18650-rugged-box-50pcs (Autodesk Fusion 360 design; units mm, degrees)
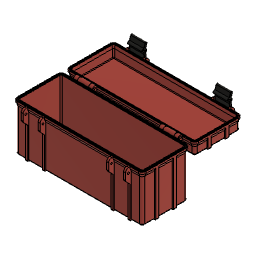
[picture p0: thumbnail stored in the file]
parameter "InnerBoxDepth" = 67 comment "Inner depth"
parameter "InnerBoxWidth" = 195 comment "Inner width"
parameter "InnerBoxBottomHeight" = 73 comment "Inner height of the bottom part"
parameter "ScrewDiameter" = 3 comment "M3 => 3 mm"
parameter "InnerCornerRadius" = 0.75 comment "Corner radius on the bottom (bottom of champfer)"
parameter "HingeLatchOffset" = 15 comment "Offset of the hinge and latch from inner wall"
parameter "WallThickness" = 2.4 comment "Thickness of the walls"
parameter "RibWidth" = 5 comment "Width of the ribs on the sides"
parameter "InnerChamferSize" = 1 comment "Size of the chamfer on the top and bottom inside the box"
parameter "ScrewThreadDiameter" = 2.85 (= "ScrewDiameter - 0.15 mm") comment "Diameter of the inner holes where you screw in the screw"
parameter "ScrewLength" = 30 comment "Length of the screw to use"
parameter "HingeWidthTolerance" = 0.25 comment "Tolerance of the hinge (width)"
parameter "RibOffset" = 17 comment "Offset of the ribs from inner wall"
parameter "LatchDistance" = 16 comment "Distance between the two screws of the latch"
parameter "InnerBoxLidHeight" = 18 comment "Inner height of the lid"
parameter "HingeLatchHolesTolerance" = 0.4 comment "Tolerance of the hinge and latch holes"
parameter "LatchWidthTolerance" = 0.4 comment "Tollerance of the latch width"
parameter "SealHeight" = 1.4 comment "Height of the seal"
parameter "HingeLatchRibWidth" = 3.2 comment "Width of the ribs for the hinges and latches"
parameter "BoxLatchRibChamferOffset" = 17
parameter "HingeRibChamferOffset" = 5 comment "Offset of the big chamfer on the rib of the hinge side"
parameter "HingeOuterDiameter" = 6.8
parameter "LidLatchRibChamferOffset" = 10 comment "Offset of the big chamfer on the rib of the lid"
parameter "HingeOuterExtend" = 3
sketch "Sketch1" plane through (0, 0, 0) normal (0, 1, 0) x axis (1, 0, 0)
  line L1 (-31.75, -96.5) -> (31.75, -96.5)
  line L2 (-32.5, 95.75) -> (-32.5, -95.75)
  line L3 (31.75, 96.5) -> (-31.75, 96.5)
  line L4 (32.5, -95.75) -> (32.5, 95.75)
  line L5 (-32.5, 96.5) -> (32.5, -96.5)
  line L6 (32.5, 96.5) -> (-32.5, -96.5)
  arc A1 centre (-31.75, 95.75) radius 0.75 clockwise from (-32.5, 95.75) to (-31.75, 96.5)
  arc A2 centre (31.75, 95.75) radius 0.75 clockwise from (31.75, 96.5) to (32.5, 95.75)
  arc A3 centre (31.75, -95.75) radius 0.75 clockwise from (32.5, -95.75) to (31.75, -96.5)
  arc A4 centre (-31.75, -95.75) radius 0.75 clockwise from (-31.75, -96.5) to (-32.5, -95.75)
  point P6 (0, 0)
  point P1 (0, 0)
  point P4 (-32.5, 96.5)
  point P5 (32.5, 96.5)
  point P2 (32.5, -96.5)
  point P3 (-32.5, -96.5)
  horizontal L1
  perpendicular L1 L2
  parallel L1 L3
  parallel L2 L4
  coincident L5 P6
  coincident L6 P6
  coincident P1 P6
  coincident P4 L3
  coincident P4 L2
  tangent L3 A1
  tangent L2 A1
  coincident P5 L3
  coincident P5 L4
  tangent L3 A2
  tangent L4 A2
  coincident P2 L4
  coincident P2 L1
  tangent L4 A3
  tangent L1 A3
  coincident P3 L1
  coincident P3 L2
  tangent L1 A4
  tangent L2 A4
  equal A1 A2
  equal A1 A4
  equal A3 A4
  dimension "d6" distance L1 L3 = 193 (= "InnerBoxWidth - 2 * InnerChamferSize")
  dimension "d7" distance L2 L4 = 65 (= "InnerBoxDepth - 2 * InnerChamferSize")
  dimension "d9" radius A2 = 0.75 (= "InnerCornerRadius")
sketch "Sketch2" plane through (0, 0, 0) normal (0, 0, 1) x axis (1, 0, 0)
  line L1 (32.5, 0) -> (0, 0)
  line L2 (32.5, 2.4) -> (32.5, 0)
  line L3 (33.5, 75.4) -> (33.5, 3.4)
  line L4 (34.73, 75.4) -> (33.5, 75.4)
  line L5 (34.73, 73.4) -> (34.73, 75.4)
  line L6 (36.53, 73.4) -> (34.73, 73.4)
  line L7 (36.53, 75.4) -> (36.53, 73.4)
  line L8 (37.76, 75.4) -> (36.53, 75.4)
  line L9 (37.76, 72.4) -> (37.76, 75.4)
  line L10 (32.5, 0) -> (42.6865, 0)
  line L11 (35.9, 72.4) -> (37.76, 72.4)
  line L12 (35.9, 68) -> (35.9, 72.4)
  line L13 (35.9, 2.4059) -> (35.9, 68)
  line L14 (37.76, 72.4) -> (35.9, 68)
  line L15 (32.5, 2.4) -> (33.5, 3.4)
  line L16 (35.9, 2.4059) -> (33.4941, 0)
  line L17 (44.76, 2.0735) -> (42.6865, 0)
  line L18 (39.76, 75.4) -> (37.76, 75.4)
  line L19 (44.76, 2.0735) -> (44.76, 70.4)
  line L20 (0, 60) -> (0, 0)
  line L21 (-44.76, 2.0735) -> (-44.76, 70.4)
  line L22 (-34.73, 73.4) -> (-34.73, 75.4)
  line L23 (-37.76, 72.4) -> (-35.9, 68)
  line L24 (-33.5, 75.4) -> (-33.5, 3.4)
  line L25 (-32.5, 2.4) -> (-32.5, 0)
  line L26 (-36.53, 73.4) -> (-34.73, 73.4)
  line L27 (-35.9, 2.4059) -> (-33.4941, 0)
  line L28 (-35.9, 2.4059) -> (-35.9, 68)
  line L29 (-32.5, 2.4) -> (-33.5, 3.4)
  line L30 (-37.76, 72.4) -> (-37.76, 75.4)
  line L31 (-44.76, 2.0735) -> (-42.6865, 0)
  line L32 (-35.9, 68) -> (-35.9, 72.4)
  line L33 (-37.76, 75.4) -> (-36.53, 75.4)
  line L34 (-36.53, 75.4) -> (-36.53, 73.4)
  line L35 (-32.5, 0) -> (-42.6865, 0)
  line L36 (-35.9, 72.4) -> (-37.76, 72.4)
  line L37 (-34.73, 75.4) -> (-33.5, 75.4)
  line L38 (33.5, 72.4) -> (35.9, 72.4)
  line L39 (-33.5, 72.4) -> (-35.9, 72.4)
  line L40 (-44.76, 70.4) -> (-44.76, 75.4)
  line L41 (-37.96, 75.4) -> (-37.76, 75.4)
  line L42 (-33.5, 62.7317) -> (-43.7642, 72.9958)
  line L43 (-39.091, 72.9958) -> (-43.7642, 72.9958)
  line L44 (-37.76, 75.4) -> (-41.36, 75.4)
  line L45 (37.76, 1.6355) -> (36.1245, 0)
  line L46 (37.76, 51.4) -> (37.76, 1.6355)
  line L47 (44.76, 58.4) -> (37.76, 51.4)
  line L48 (-37.76, 1.6355) -> (-36.1245, 0)
  line L49 (-37.76, 63.4) -> (-37.76, 1.6355)
  line L50 (-44.76, 70.4) -> (-37.76, 63.4)
  arc A1 centre (39.76, 70.4) radius 5 clockwise from (39.76, 75.4) to (44.76, 70.4)
  circle C1 centre (40.26, 67.4) radius 1.7
  circle C2 centre (-41.36, 75.4) radius 1.7
  circle C3 centre (-41.36, 75.4) radius 3.4
  point P1 (0, 0)
  point P2 (0, 0)
  point P15 (33.4941, 0)
  point P18 (44.76, 75.4)
  point P24 (0, 0)
  point P3 (32.5, 0)
  point P40 (-32.5, 0)
  point P4 (32.5, 2.4)
  point P42 (-32.5, 2.4)
  point P5 (33.5, 75.4)
  point P38 (-33.5, 75.4)
  point P6 (34.73, 75.4)
  point P41 (-34.73, 75.4)
  point P7 (34.73, 73.4)
  point P43 (-34.73, 73.4)
  point P8 (36.53, 73.4)
  point P39 (-36.53, 73.4)
  point P9 (36.53, 75.4)
  point P34 (-36.53, 75.4)
  point P10 (37.76, 75.4)
  point P30 (-37.76, 75.4)
  point P11 (37.76, 72.4)
  point P33 (-37.76, 72.4)
  point P12 (35.9, 72.4)
  point P36 (-35.9, 72.4)
  point P13 (35.9, 68)
  point P29 (-35.9, 68)
  point P14 (33.5, 3.4)
  point P35 (-33.5, 3.4)
  point P32 (-33.4941, 0)
  point P16 (35.9, 2.4059)
  point P27 (-35.9, 2.4059)
  point P17 (42.6865, 0)
  point P26 (-42.6865, 0)
  point P37 (-44.76, 75.4)
  point P19 (44.76, 2.0735)
  point P31 (-44.76, 2.0735)
  point P21 (44.76, 70.4)
  point P28 (-44.76, 70.4)
  point P44 (33.5, 72.4)
  point P45 (-33.5, 72.4)
  point P48 (-44.76, 75.4)
  point P49 (-37.96, 75.4)
  point P50 (-43.7642, 72.9958)
  point P52 (-33.5, 62.7317)
  point P46 (-41.36, 75.4)
  point P53 (-41.36, 75.4)
  point P54 (36.1245, 0)
  point P57 (44.76, 58.4)
  point P58 (-36.1245, 0)
  point P55 (37.76, 1.6355)
  point P59 (-37.76, 1.6355)
  point P61 (-44.76, 70.4)
  point P23 (40.26, 67.4)
  coincident P1 P2
  horizontal L1
  perpendicular L1 L2
  perpendicular L3 L4
  perpendicular L4 L5
  perpendicular L5 L6
  perpendicular L6 L7
  perpendicular L7 L8
  perpendicular L8 L9
  perpendicular L2 L10
  perpendicular L9 L11
  perpendicular L11 L12
  perpendicular L10 L13
  coincident L10 P15
  vertical L3
  perpendicular L9 L18
  perpendicular L8 L19
  coincident P18 L18
  coincident P18 L19
  tangent L18 A1
  tangent L19 A1
  coincident P1 P24
  perpendicular L1 L20
  symmetric P3 L20 P40
  symmetric P4 L20 P42
  symmetric P5 L20 P38
  symmetric P6 L20 P41
  symmetric P7 L20 P43
  symmetric P8 L20 P39
  symmetric P9 L20 P34
  symmetric P10 L20 P30
  symmetric P11 L20 P33
  symmetric P12 L20 P36
  symmetric P13 L20 P29
  symmetric P14 L20 P35
  symmetric P15 L20 P32
  symmetric P16 L20 P27
  symmetric P17 L20 P26
  symmetric P18 L20 P37
  symmetric P19 L20 P31
  symmetric P21 L20 P28
  coincident L3 P44
  perpendicular L3 L38
  coincident L24 P45
  perpendicular L24 L39
  concentric C2 C3
  coincident P37 P48
  coincident C3 P49
  horizontal L43
  coincident C3 P50
  tangent C3 L42
  coincident L24 P52
  coincident P46 P53
  perpendicular L30 L44
  horizontal L41
  coincident L10 P54
  perpendicular L10 L46
  coincident L19 P57
  collinear L9 L46
  parallel L16 L45
  symmetric L20 P54 P58
  symmetric L20 P55 P59
  parallel L45 L47
  parallel L28 L49
  coincident L21 P61
  parallel L48 L50
  dimension "d12" distance P2 P3 = 32.5 (= "InnerBoxDepth / 2 - InnerChamferSize")
  dimension "d13" distance P3 P4 = 2.4 (= "WallThickness")
  dimension "d15" distance P5 P6 = 1.23
  dimension "d16" distance P6 P7 = 2
  dimension "d17" distance P7 P8 = 1.8
  dimension "d18" distance P8 P9 = 2
  dimension "d20" distance P10 P11 = 3
  dimension "d23" distance P12 P13 = 4.4
  dimension "d26" distance L15 L16 = 2.4 (= "WallThickness")
  dimension "d27" distance P4 P14 = 1 (= "InnerChamferSize")
  dimension "d28" distance P4 P14 = 1 (= "InnerChamferSize")
  dimension "d29" distance P3 L8 = 75.4 (= "InnerBoxBottomHeight + WallThickness")
  dimension "d30" distance L16 L17 = 6.5
  dimension "d61" distance P10 P18 = 7
  dimension "d62" radius A1 = 5
  dimension "d63" diameter C1 = 3.4 (= "ScrewDiameter + HingeLatchHolesTolerance")
  dimension "d64" distance L18 P23 = 8 (= "LatchDistance / 2")
  dimension "d65" distance L19 P23 = 4.5
  dimension "d129" distance L7 L9 = 1.23
  dimension "d131" distance L3 L13 = 2.4 (= "WallThickness")
  dimension "d137" diameter C2 = 3.4 (= "ScrewDiameter + HingeLatchHolesTolerance")
  dimension "d138" distance P30 P46 = 3.6 (= "HingeOuterDiameter / 2 + 0.2 mm")
  dimension "d139" diameter C3 = 6.8 (= "HingeOuterDiameter")
  dimension "d140" angle L42 L43 = 45
  dimension "d111" distance L16 L45 = 1.86 (= "d113")
  dimension "d113" distance L9 L12 = 1.86
  dimension "d114" distance L18 P57 = 17 (= "BoxLatchRibChamferOffset")
  dimension "d123" distance L44 P61 = 5 (= "HingeRibChamferOffset")
extrude "Extrude1" new body sketch "Sketch1" profile of L1 L2 L3 L4 A1 A2 A3 A4 along normal blind 2.4 (= "WallThickness")
sweep "Sweep1" sketch "Sketch2" TwistAngle 0 TaperAngle 0
work_plane "WorkPlane2" AlongDistance -16.5 (= "RibOffset - InnerBoxDepth / 2")
sketch "Sketch4" plane through (-16.5, 0, 0) normal (1, 0, 0) x axis (0, 0, -1)
  line L1 (-96.5, 0) -> (0, 0)
  line L2 (-96.5, 2.4) -> (-96.5, 0)
  line L3 (-97.5, 2.4) -> (-96.5, 2.4)
  line L4 (-97.5, 3.4) -> (-97.5, 2.4)
  line L5 (-96.5, 2.4) -> (-97.5, 3.4)
  line L6 (-97.5, 5) -> (-97.5, 2.4)
  line L7 (-97.5, 72.4) -> (-97.5, 2.4)
  line L8 (-101.76, 72.4) -> (-97.5, 72.4)
  line L9 (-101.76, 1.6355) -> (-101.76, 72.4)
  line L10 (-96.5, 0) -> (-100.1245, 0)
  line L11 (-101.76, 1.6355) -> (-100.1245, 0)
  line L12 (0, 70) -> (0, 0)
  line L13 (101.76, 1.6355) -> (100.1245, 0)
  line L14 (96.5, 0) -> (100.1245, 0)
  line L15 (97.5, 5) -> (97.5, 2.4)
  line L16 (97.5, 72.4) -> (97.5, 2.4)
  line L17 (96.5, 2.4) -> (97.5, 3.4)
  line L18 (97.5, 3.4) -> (97.5, 2.4)
  line L19 (101.76, 72.4) -> (97.5, 72.4)
  line L20 (101.76, 1.6355) -> (101.76, 72.4)
  line L21 (96.5, 2.4) -> (96.5, 0)
  line L22 (97.5, 2.4) -> (96.5, 2.4)
  point P1 (0, 0)
  point P2 (0, 0)
  point P7 (-97.5, 5)
  point P12 (0, 0)
  point P3 (-96.5, 0)
  point P16 (96.5, 0)
  point P4 (-96.5, 2.4)
  point P18 (96.5, 2.4)
  point P5 (-97.5, 2.4)
  point P15 (97.5, 2.4)
  point P6 (-97.5, 3.4)
  point P17 (97.5, 3.4)
  point P22 (97.5, 5)
  point P8 (-97.5, 72.4)
  point P14 (97.5, 72.4)
  point P9 (-101.76, 72.4)
  point P19 (101.76, 72.4)
  point P10 (-101.76, 1.6355)
  point P21 (101.76, 1.6355)
  point P11 (-100.1245, 0)
  point P20 (100.1245, 0)
  coincident P1 P2
  horizontal L1
  perpendicular L1 L2
  perpendicular L2 L3
  perpendicular L3 L4
  coincident L4 P7
  perpendicular L3 L7
  perpendicular L7 L8
  perpendicular L8 L9
  perpendicular L2 L10
  coincident P1 P12
  perpendicular L1 L12
  symmetric P3 L12 P16
  symmetric P4 L12 P18
  symmetric P5 L12 P15
  symmetric P6 L12 P17
  symmetric P7 L12 P22
  symmetric P8 L12 P14
  symmetric P9 L12 P19
  symmetric P10 L12 P21
  symmetric P11 L12 P20
  dimension "d47" distance P2 P3 = 96.5 (= "InnerBoxWidth / 2 - InnerChamferSize")
  dimension "d48" distance P3 P4 = 2.4 (= "WallThickness")
  dimension "d49" distance P4 P5 = 1 (= "InnerChamferSize")
  dimension "d50" distance P5 P6 = 1 (= "InnerChamferSize")
  dimension "d52" distance P8 P9 = 4.26
  dimension "d53" distance L5 L11 = 4.26 (= "d52")
  dimension "d56" distance L8 L10 = 72.4 (= "InnerBoxBottomHeight - 3 mm + WallThickness")
extrude "Extrude2" add sketch "Sketch4" profile of L2 L3 L4 L5 L6 L7 L8 L9 L10 L11 L13 L14 L15 L16 L17 L18 L19 L20 L21 L22 along a picked direction blind 5 (= "RibWidth")
work_plane "WorkPlane3" AlongDistance 16.5 (= "InnerBoxDepth / 2 - RibOffset")
sketch "Sketch5" plane through (16.5, 0, 0) normal (1, 0, 0) x axis (0, 0, -1)
  line L1 (-97.5, 72.4) -> (-97.5, 2.4)
  line L2 (-96.5, 2.4) -> (-97.5, 3.4)
  line L3 (-97.5, 2.4) -> (-96.5, 2.4)
  line L4 (-96.5, 2.4) -> (-96.5, 0)
  line L5 (-96.5, 0) -> (-100.1245, 0)
  line L6 (-101.76, 1.6355) -> (-100.1245, 0)
  line L7 (-101.76, 1.6355) -> (-101.76, 72.4)
  line L8 (-101.76, 72.4) -> (-97.5, 72.4)
  line L9 (101.76, 72.4) -> (97.5, 72.4)
  line L10 (101.76, 1.6355) -> (101.76, 72.4)
  line L11 (97.5, 72.4) -> (97.5, 2.4)
  line L12 (96.5, 2.4) -> (97.5, 3.4)
  line L13 (97.5, 2.4) -> (96.5, 2.4)
  line L14 (101.76, 1.6355) -> (100.1245, 0)
  line L15 (96.5, 2.4) -> (96.5, 0)
  line L16 (96.5, 0) -> (100.1245, 0)
extrude "Extrude3" add sketch "Sketch5" along a picked direction no distance stored
work_plane "WorkPlane4" AlongDistance -82.5 (= "HingeLatchOffset - InnerBoxWidth / 2")
sketch "Sketch6" plane through (0, 0, -82.5) normal (0, 0, 1) x axis (1, 0, 0)
  line L1 (39.76, 75.4) -> (37.76, 75.4)
  line L2 (44.76, 2.0735) -> (44.76, 70.4)
  line L3 (44.76, 2.0735) -> (42.6865, 0)
  line L4 (32.5, 0) -> (42.6865, 0)
  line L5 (32.5, 2.4) -> (32.5, 0)
  line L6 (32.5, 2.4) -> (33.5, 3.4)
  line L7 (33.5, 75.4) -> (33.5, 3.4)
  line L8 (33.5, 72.4) -> (35.9, 72.4)
  line L9 (35.9, 72.4) -> (37.76, 72.4)
  line L10 (37.76, 72.4) -> (37.76, 75.4)
  line L11 (-33.5, 75.4) -> (-33.5, 3.4)
  line L12 (-33.5, 72.4) -> (-35.9, 72.4)
  line L13 (-35.9, 72.4) -> (-37.76, 72.4)
  line L14 (-37.76, 72.4) -> (-37.76, 75.4)
  line L15 (-44.76, 2.0735) -> (-44.76, 70.4)
  line L16 (-44.76, 2.0735) -> (-42.6865, 0)
  line L17 (-32.5, 0) -> (-42.6865, 0)
  line L18 (-32.5, 2.4) -> (-32.5, 0)
  line L19 (-32.5, 2.4) -> (-33.5, 3.4)
  line L20 (-44.76, 70.4) -> (-44.76, 75.4)
  line L21 (-37.96, 75.4) -> (-37.76, 75.4)
  line L22 (-33.5, 62.7317) -> (-43.7642, 72.9958)
  line L23 (44.76, 58.4) -> (37.76, 51.4)
  line L24 (37.76, 51.4) -> (37.76, 1.6355)
  line L25 (37.76, 1.6355) -> (36.1245, 0)
  line L26 (-37.76, 1.6355) -> (-36.1245, 0)
  line L27 (-37.76, 63.4) -> (-37.76, 1.6355)
  line L28 (-44.76, 70.4) -> (-37.76, 63.4)
  arc A1 centre (39.76, 70.4) radius 5 clockwise from (39.76, 75.4) to (44.76, 70.4)
  circle C1 centre (40.26, 67.4) radius 1.7
  circle C2 centre (-41.36, 75.4) radius 3.4
  circle C3 centre (-41.36, 75.4) radius 1.7
extrude "Extrude10" add sketch "Sketch6" profile of L1 L2 A1 L4 L5 L6 L7 L8 L9 L10 L11 L12 L13 L14 L15 L17 L18 L19 C1 L20 C2 C3 L21 L22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 along a picked direction blind 3.2 (= "HingeLatchRibWidth")
extrude "Extrude17" add sketch "Sketch6" profile of L11 L12 L13 L14 C2 C3 L21 L22 along a picked direction blind 6.2 (= "HingeLatchRibWidth + HingeOuterExtend")
work_plane "WorkPlane5" AlongDistance 30 (= "ScrewLength")
sketch "Sketch7" plane through (0, 0, -52.5) normal (0, 0, 1) x axis (1, 0, 0)
  line L1 (-32.5, 2.4) -> (-32.5, 0)
  line L2 (-32.5, 2.4) -> (-33.5, 3.4)
  line L3 (-33.5, 75.4) -> (-33.5, 3.4)
  line L4 (-33.5, 72.4) -> (-35.9, 72.4)
  line L5 (-35.9, 72.4) -> (-37.76, 72.4)
  line L6 (-37.76, 72.4) -> (-37.76, 75.4)
  line L7 (-44.76, 2.0735) -> (-44.76, 70.4)
  line L8 (-44.76, 2.0735) -> (-42.6865, 0)
  line L9 (-32.5, 0) -> (-42.6865, 0)
  line L10 (32.5, 2.4) -> (32.5, 0)
  line L11 (32.5, 2.4) -> (33.5, 3.4)
  line L12 (33.5, 75.4) -> (33.5, 3.4)
  line L13 (33.5, 72.4) -> (35.9, 72.4)
  line L14 (35.9, 72.4) -> (37.76, 72.4)
  line L15 (37.76, 72.4) -> (37.76, 75.4)
  line L16 (39.76, 75.4) -> (37.76, 75.4)
  line L17 (44.76, 2.0735) -> (44.76, 70.4)
  line L18 (44.76, 2.0735) -> (42.6865, 0)
  line L19 (32.5, 0) -> (42.6865, 0)
  line L20 (-44.76, 70.4) -> (-44.76, 75.4)
  line L21 (-37.96, 75.4) -> (-37.76, 75.4)
  line L22 (-33.5, 62.7317) -> (-43.7642, 72.9958)
  line L23 (-37.76, 1.6355) -> (-36.1245, 0)
  line L24 (44.76, 58.4) -> (37.76, 51.4)
  line L25 (37.76, 51.4) -> (37.76, 1.6355)
  line L26 (37.76, 1.6355) -> (36.1245, 0)
  line L27 (-37.76, 63.4) -> (-37.76, 1.6355)
  line L28 (-44.76, 70.4) -> (-37.76, 63.4)
  arc A1 centre (39.76, 70.4) radius 5 clockwise from (39.76, 75.4) to (44.76, 70.4)
  circle C1 centre (40.26, 67.4) radius 1.7
  circle C2 centre (-41.36, 75.4) radius 3.4
  circle C3 centre (-41.36, 75.4) radius 1.7
  circle C4 centre (40.26, 67.4) radius 1.425
  circle C5 centre (-41.36, 75.4) radius 1.425
  concentric C1 C4
  concentric C2 C5
  dimension "d24" diameter C4 = 2.85 (= "ScrewThreadDiameter")
  dimension "d25" diameter C5 = 2.85 (= "ScrewThreadDiameter")
extrude "Extrude11" add sketch "Sketch7" profile of L1 L2 L3 L4 L5 L6 L7 L9 L10 L11 L12 L13 L14 L15 L16 A1 L17 L19 L20 C2 L21 L22 C4 C5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 along a picked direction no distance stored
extrude "Extrude18" add sketch "Sketch7" profile of L3 L4 L5 L6 C2 L21 L22 C5 along a picked direction no distance stored
work_plane "WorkPlane6" AlongDistance 82.5 (= "-( HingeLatchOffset - InnerBoxWidth / 2 )")
sketch "Sketch8" plane through (0, 0, 82.5) normal (0, 0, 1) x axis (1, 0, 0)
  line L1 (-44.76, 2.0735) -> (-44.76, 70.4)
  line L2 (-37.76, 72.4) -> (-37.76, 75.4)
  line L3 (-35.9, 72.4) -> (-37.76, 72.4)
  line L4 (-33.5, 72.4) -> (-35.9, 72.4)
  line L5 (-33.5, 75.4) -> (-33.5, 3.4)
  line L6 (-32.5, 2.4) -> (-33.5, 3.4)
  line L7 (-32.5, 2.4) -> (-32.5, 0)
  line L8 (-32.5, 0) -> (-42.6865, 0)
  line L9 (-44.76, 2.0735) -> (-42.6865, 0)
  line L10 (32.5, 2.4) -> (32.5, 0)
  line L11 (32.5, 2.4) -> (33.5, 3.4)
  line L12 (33.5, 75.4) -> (33.5, 3.4)
  line L13 (33.5, 72.4) -> (35.9, 72.4)
  line L14 (35.9, 72.4) -> (37.76, 72.4)
  line L15 (37.76, 72.4) -> (37.76, 75.4)
  line L16 (39.76, 75.4) -> (37.76, 75.4)
  line L17 (44.76, 2.0735) -> (44.76, 70.4)
  line L18 (44.76, 2.0735) -> (42.6865, 0)
  line L19 (32.5, 0) -> (42.6865, 0)
  line L20 (-44.76, 70.4) -> (-44.76, 75.4)
  line L21 (-37.96, 75.4) -> (-37.76, 75.4)
  line L22 (-33.5, 62.7317) -> (-43.7642, 72.9958)
  line L23 (44.76, 58.4) -> (37.76, 51.4)
  line L24 (37.76, 51.4) -> (37.76, 1.6355)
  line L25 (37.76, 1.6355) -> (36.1245, 0)
  line L26 (-37.76, 1.6355) -> (-36.1245, 0)
  line L27 (-37.76, 63.4) -> (-37.76, 1.6355)
  line L28 (-44.76, 70.4) -> (-37.76, 63.4)
  arc A1 centre (39.76, 70.4) radius 5 clockwise from (39.76, 75.4) to (44.76, 70.4)
  circle C1 centre (40.26, 67.4) radius 1.7
  circle C2 centre (-41.36, 75.4) radius 3.4
  circle C3 centre (-41.36, 75.4) radius 1.7
extrude "Extrude12" add sketch "Sketch8" profile of L1 L2 L3 L4 L5 L6 L7 L8 L10 L11 L12 L13 L14 L15 L16 A1 L17 C1 L19 L20 C2 C3 L21 L22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 along a picked direction no distance stored
extrude "Extrude19" add sketch "Sketch8" profile of L2 L3 L4 L5 C2 C3 L21 L22 along a picked direction no distance stored
work_plane "WorkPlane7"
sketch "Sketch9" plane through (0, 0, 52.5) normal (0, 0, 1) x axis (1, 0, 0)
  line L1 (44.76, 2.0735) -> (42.6865, 0)
  line L2 (32.5, 0) -> (42.6865, 0)
  line L3 (44.76, 2.0735) -> (44.76, 70.4)
  line L4 (39.76, 75.4) -> (37.76, 75.4)
  line L5 (37.76, 72.4) -> (37.76, 75.4)
  line L6 (35.9, 72.4) -> (37.76, 72.4)
  line L7 (33.5, 72.4) -> (35.9, 72.4)
  line L8 (33.5, 75.4) -> (33.5, 3.4)
  line L9 (32.5, 2.4) -> (33.5, 3.4)
  line L10 (32.5, 2.4) -> (32.5, 0)
  line L11 (-32.5, 2.4) -> (-32.5, 0)
  line L12 (-32.5, 2.4) -> (-33.5, 3.4)
  line L13 (-33.5, 75.4) -> (-33.5, 3.4)
  line L14 (-33.5, 72.4) -> (-35.9, 72.4)
  line L15 (-35.9, 72.4) -> (-37.76, 72.4)
  line L16 (-37.76, 72.4) -> (-37.76, 75.4)
  line L17 (-44.76, 2.0735) -> (-44.76, 70.4)
  line L18 (-44.76, 2.0735) -> (-42.6865, 0)
  line L19 (-32.5, 0) -> (-42.6865, 0)
  line L20 (-44.76, 70.4) -> (-44.76, 75.4)
  line L21 (-37.96, 75.4) -> (-37.76, 75.4)
  line L22 (-33.5, 62.7317) -> (-43.7642, 72.9958)
  line L23 (44.76, 58.4) -> (37.76, 51.4)
  line L24 (37.76, 51.4) -> (37.76, 1.6355)
  line L25 (37.76, 1.6355) -> (36.1245, 0)
  line L26 (-37.76, 1.6355) -> (-36.1245, 0)
  line L27 (-37.76, 63.4) -> (-37.76, 1.6355)
  line L28 (-44.76, 70.4) -> (-37.76, 63.4)
  arc A1 centre (39.76, 70.4) radius 5 clockwise from (39.76, 75.4) to (44.76, 70.4)
  circle C1 centre (40.26, 67.4) radius 1.7
  circle C2 centre (-41.36, 75.4) radius 3.4
  circle C3 centre (-41.36, 75.4) radius 1.7
  circle C4 centre (40.26, 67.4) radius 1.425
  circle C5 centre (-41.36, 75.4) radius 1.425
  concentric C1 C4
  concentric C2 C5
  dimension "d39" diameter C4 = 2.85 (= "ScrewThreadDiameter")
  dimension "d40" diameter C5 = 2.85 (= "ScrewThreadDiameter")
extrude "Extrude13" add sketch "Sketch9" profile of L2 L3 A1 L4 L5 L6 L7 L8 L9 L10 L11 L12 L13 L14 L15 L16 L17 L19 L20 C2 L21 L22 C4 C5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 along a picked direction blind 3.2 (= "HingeLatchRibWidth")
extrude "Extrude20" add sketch "Sketch9" profile of L13 L14 L15 L16 C2 L21 L22 C5 along a picked direction blind 6.2 (= "HingeLatchRibWidth + HingeOuterExtend")
fillet "Fillet2" radius 1
fillet "Fillet3" radius 3
component_from_bodies "Body->Comp1"
sketch "Sketch10" plane through (0, 0, 0) normal (0, 0, 1) x axis (1, 0, 0)
  line L1 (156.2863, 42.7568) -> (153.4854, 42.7568)
  line L2 (149.3136, 34.5236) -> (152.4867, 44.0068)
  line L3 (147.7963, 35.0313) -> (150.9693, 44.5145)
  line L4 (150.8309, 34.0159) -> (154.004, 43.4992)
  line L5 (152.8792, 47.9875) -> (152.4973, 45.6068)
  line L6 (152.4867, 44.0068) -> (152.4867, 60.0068)
  circle C1 centre (152.4867, 44.0068) radius 1.6
  circle C2 centre (152.4867, 44.0068) radius 4
  circle C3 centre (152.4867, 60.0068) radius 1.6
  circle C4 centre (152.4867, 60.0068) radius 4
  arc A1 centre (171.1154, 52.0068) radius 20.2738 clockwise from (152.4867, 44.0068) to (152.4867, 60.0068)
  arc A2 centre (171.1154, 52.0068) radius 21.8738 clockwise from (151.0165, 43.3755) to (151.0165, 60.6382)
  arc A3 centre (171.1154, 52.0068) radius 18.6738 clockwise from (153.9568, 44.6382) to (153.9568, 59.3755)
  circle C5 centre (149.3136, 34.5236) radius 1.6
  point P3 (152.4867, 44.0068)
  point P4 (152.4867, 44.0068)
  point P5 (152.4867, 60.0068)
  point P6 (152.4867, 60.0068)
  point P15 (153.4854, 42.7568)
  point P16 (156.2863, 42.7568)
  point P2 (152.4867, 44.0068)
  point P17 (152.4867, 44.0068)
  point P18 (149.3136, 34.5236)
  point P19 (149.3136, 34.5236)
  point P24 (152.4973, 45.6068)
  point P25 (152.8792, 47.9875)
  point P26 (152.4867, 60.0068)
  point P27 (152.4867, 44.0068)
  point P14 (153.9568, 59.3755)
  point P11 (151.0165, 60.6382)
  point P10 (151.0165, 43.3755)
  point P13 (153.9568, 44.6382)
  point P22 (154.004, 43.4992)
  point P20 (150.9693, 44.5145)
  point P21 (147.7963, 35.0313)
  point P23 (150.8309, 34.0159)
  concentric C1 C2
  coincident P3 P4
  coincident P5 P6
  concentric C3 C4
  coincident C1 P15
  coincident C2 P16
  coincident P2 P17
  coincident P18 P19
  coincident C1 P24
  coincident A3 P25
  coincident C2 P25
  concentric A1 A3
  concentric A1 A2
  coincident P6 P26
  coincident P2 P27
  vertical L6
  coincident C3 P14
  tangent C3 A3
  tangent C3 A2
  coincident C3 P11
  coincident C1 P10
  coincident C1 P13
  parallel L2 L3
  parallel L2 L4
  coincident C1 P22
  coincident C1 P20
  tangent C1 L3
  tangent C1 L4
  coincident C5 P21
  coincident C5 P23
  horizontal L1
  dimension "d98" diameter C1 = 3.2 (= "ScrewDiameter + 0.2 mm")
  dimension "d99" diameter C2 = 8
  dimension "d100" distance P4 P5 = 16 (= "LatchDistance")
  dimension "d101" diameter C3 = 3.2 (= "ScrewDiameter + 0.2 mm")
  dimension "d102" diameter C4 = 8
  dimension "d105" diameter C5 = 3.2 (= "ScrewDiameter + 0.2 mm")
  dimension "d66" distance P17 P18 = 10
  dimension "d67" angle L2 L6 = 161.5
  dimension "d69" distance P2 L1 = 1.25
extrude "Extrude15" new body sketch "Sketch10" profile of C1 C2 C3 C4 A1 A2 A3 L1 L2 C5 L3 L4 L5 along a picked direction blind 23.2 (= "( ScrewLength - 2 * HingeLatchRibWidth ) - LatchWidthTolerance")
component_from_bodies "Body->Comp3"
sketch "Sketch1" plane through (0, 0, 0) normal (0, 1, 0) x axis (1, 0, 0)
  line L1 (-31.75, -96.5) -> (31.75, -96.5)
  line L2 (-32.5, 95.75) -> (-32.5, -95.75)
  line L3 (31.75, 96.5) -> (-31.75, 96.5)
  line L4 (32.5, -95.75) -> (32.5, 95.75)
  line L5 (-32.5, 96.5) -> (32.5, -96.5)
  line L6 (32.5, 96.5) -> (-32.5, -96.5)
  arc A1 centre (-31.75, 95.75) radius 0.75 clockwise from (-32.5, 95.75) to (-31.75, 96.5)
  arc A2 centre (31.75, 95.75) radius 0.75 clockwise from (31.75, 96.5) to (32.5, 95.75)
  arc A3 centre (31.75, -95.75) radius 0.75 clockwise from (32.5, -95.75) to (31.75, -96.5)
  arc A4 centre (-31.75, -95.75) radius 0.75 clockwise from (-31.75, -96.5) to (-32.5, -95.75)
  point P6 (0, 0)
  point P1 (0, 0)
  point P4 (-32.5, 96.5)
  point P5 (32.5, 96.5)
  point P2 (32.5, -96.5)
  point P3 (-32.5, -96.5)
  horizontal L1
  perpendicular L1 L2
  parallel L1 L3
  parallel L2 L4
  coincident L5 P6
  coincident L6 P6
  coincident P1 P6
  coincident P4 L3
  coincident P4 L2
  tangent L3 A1
  tangent L2 A1
  coincident P5 L3
  coincident P5 L4
  tangent L3 A2
  tangent L4 A2
  coincident P2 L4
  coincident P2 L1
  tangent L4 A3
  tangent L1 A3
  coincident P3 L1
  coincident P3 L2
  tangent L1 A4
  tangent L2 A4
  equal A1 A2
  equal A1 A4
  equal A3 A4
  dimension "d6_1" distance L1 L3 = 193 (= "InnerBoxWidth - 2 * InnerChamferSize")
  dimension "d7_1" distance L2 L4 = 65 (= "InnerBoxDepth - 2 * InnerChamferSize")
  dimension "d9_1" radius A2 = 0.75 (= "InnerCornerRadius")
sketch "Sketch2" plane through (0, 0, 0) normal (0, 0, 1) x axis (1, 0, 0)
  line L1 (32.5, 0) -> (0, 0)
  line L2 (32.5, 2.4) -> (32.5, 0)
  line L3 (33.5, 20.4) -> (33.5, 3.4)
  line L4 (34.73, 20.4) -> (33.5, 20.4)
  line L5 (34.73, 18.4) -> (34.73, 20.4)
  line L6 (36.53, 18.4) -> (34.73, 18.4)
  line L7 (36.53, 20.4) -> (36.53, 18.4)
  line L8 (37.76, 20.4) -> (36.53, 20.4)
  line L9 (37.76, 17.4) -> (37.76, 20.4)
  line L10 (32.5, 0) -> (42.6865, 0)
  line L11 (35.9, 17.4) -> (37.76, 17.4)
  line L12 (35.9, 13) -> (35.9, 17.4)
  line L13 (35.9, 2.4059) -> (35.9, 13)
  line L14 (37.76, 17.4) -> (35.9, 13)
  line L15 (32.5, 2.4) -> (33.5, 3.4)
  line L16 (35.9, 2.4059) -> (33.4941, 0)
  line L17 (44.76, 2.0735) -> (42.6865, 0)
  line L18 (39.76, 20.4) -> (37.76, 20.4)
  line L19 (44.76, 2.0735) -> (44.76, 15.4)
  line L20 (0, 60) -> (0, 0)
  line L21 (-34.73, 18.4) -> (-34.73, 20.4)
  line L22 (-37.76, 17.4) -> (-35.9, 13)
  line L23 (-33.5, 20.4) -> (-33.5, 3.4)
  line L24 (-32.5, 2.4) -> (-32.5, 0)
  line L25 (-36.53, 18.4) -> (-34.73, 18.4)
  line L26 (-35.9, 2.4059) -> (-33.4941, 0)
  line L27 (-35.9, 2.4059) -> (-35.9, 13)
  line L28 (-32.5, 2.4) -> (-33.5, 3.4)
  line L29 (-37.76, 17.4) -> (-37.76, 20.4)
  line L30 (-35.9, 13) -> (-35.9, 17.4)
  line L31 (-37.76, 20.4) -> (-36.53, 20.4)
  line L32 (-36.53, 20.4) -> (-36.53, 18.4)
  line L33 (-35.9, 17.4) -> (-37.76, 17.4)
  line L34 (-34.73, 20.4) -> (-33.5, 20.4)
  line L35 (33.5, 17.4) -> (35.9, 17.4)
  line L36 (-33.5, 17.4) -> (-35.9, 17.4)
  line L37 (36.53, 20.4) -> (34.73, 20.4)
  line L38 (35.63, 21.3) -> (35.63, 20.4)
  line L39 (35.83, 21.3) -> (35.63, 21.3)
  line L40 (35.83, 21.06) -> (35.83, 21.3)
  line L41 (35.43, 21.3) -> (35.63, 21.3)
  line L42 (35.43, 21.06) -> (35.43, 21.3)
  line L43 (34.88, 18.4) -> (34.88, 20.4)
  line L44 (36.38, 20.4) -> (36.38, 18.4)
  line L45 (35.63, 21.3) -> (34.88, 20.4)
  line L46 (36.38, 20.4) -> (35.63, 21.3)
  line L47 (-37.96, 20.4) -> (-37.76, 20.4)
  line L48 (-35.9, 10.1317) -> (-43.7642, 17.9958)
  line L49 (-89.0433, 17.9958) -> (-43.7642, 17.9958)
  line L50 (-33.4941, 0) -> (-32.5, 0)
  line L51 (-32.5, 0) -> (-42.6865, 0)
  line L52 (-44.76, 2.0735) -> (-42.6865, 0)
  line L53 (-44.76, 2.0735) -> (-44.76, 15.4)
  line L54 (-44.76, 20.4) -> (-44.76, 15.4)
  line L55 (-37.76, 20.4) -> (-41.36, 20.4)
  line L56 (37.76, 1.6355) -> (36.1245, 0)
  line L57 (37.76, 3.4) -> (37.76, 1.6355)
  line L58 (44.76, 10.4) -> (37.76, 3.4)
  line L59 (-37.76, 1.6355) -> (-36.1245, 0)
  line L60 (-37.76, 8.4) -> (-37.76, 1.6355)
  line L61 (-44.76, 15.4) -> (-37.76, 8.4)
  arc A1 centre (39.76, 15.4) radius 5 clockwise from (39.76, 20.4) to (44.76, 15.4)
  circle C1 centre (40.26, 12.4) radius 1.7
  circle C2 centre (-41.36, 20.4) radius 1.7
  circle C3 centre (-41.36, 20.4) radius 3.4
  point P1 (0, 0)
  point P2 (0, 0)
  point P15 (33.4941, 0)
  point P18 (44.76, 20.4)
  point P24 (0, 0)
  point P3 (32.5, 0)
  point P37 (-32.5, 0)
  point P4 (32.5, 2.4)
  point P39 (-32.5, 2.4)
  point P5 (33.5, 20.4)
  point P35 (-33.5, 20.4)
  point P6 (34.73, 20.4)
  point P38 (-34.73, 20.4)
  point P7 (34.73, 18.4)
  point P40 (-34.73, 18.4)
  point P8 (36.53, 18.4)
  point P36 (-36.53, 18.4)
  point P9 (36.53, 20.4)
  point P31 (-36.53, 20.4)
  point P10 (37.76, 20.4)
  point P28 (-37.76, 20.4)
  point P11 (37.76, 17.4)
  point P30 (-37.76, 17.4)
  point P12 (35.9, 17.4)
  point P33 (-35.9, 17.4)
  point P13 (35.9, 13)
  point P27 (-35.9, 13)
  point P14 (33.5, 3.4)
  point P32 (-33.5, 3.4)
  point P29 (-33.4941, 0)
  point P16 (35.9, 2.4059)
  point P26 (-35.9, 2.4059)
  point P34 (-44.76, 20.4)
  point P41 (33.5, 17.4)
  point P42 (-33.5, 17.4)
  point P43 (35.63, 20.4)
  point P47 (34.88, 20.4)
  point P48 (34.88, 18.4)
  point P49 (36.38, 18.4)
  point P50 (36.38, 20.4)
  point P51 (35.43, 21.06)
  point P52 (35.83, 21.06)
  point P55 (-37.96, 20.4)
  point P56 (-43.7642, 17.9958)
  point P57 (-35.9, 10.1317)
  point P60 (-32.5, 0)
  point P17 (42.6865, 0)
  point P59 (-42.6865, 0)
  point P19 (44.76, 2.0735)
  point P61 (-44.76, 2.0735)
  point P21 (44.76, 15.4)
  point P62 (-44.76, 15.4)
  point P63 (-44.76, 20.4)
  point P54 (-41.36, 20.4)
  point P64 (-41.36, 20.4)
  point P65 (36.1245, 0)
  point P68 (44.76, 10.4)
  point P70 (-36.1245, 0)
  point P66 (37.76, 1.6355)
  point P69 (-37.76, 1.6355)
  point P72 (-44.76, 15.4)
  point P23 (40.26, 12.4)
  point P46 (35.43, 21.3)
  point P45 (35.83, 21.3)
  point P53 (-41.36, 20.4)
  coincident P1 P2
  horizontal L1
  perpendicular L1 L2
  perpendicular L3 L4
  perpendicular L4 L5
  perpendicular L5 L6
  perpendicular L6 L7
  perpendicular L7 L8
  perpendicular L8 L9
  perpendicular L2 L10
  perpendicular L9 L11
  perpendicular L11 L12
  perpendicular L10 L13
  coincident L10 P15
  vertical L3
  perpendicular L9 L18
  perpendicular L8 L19
  coincident P18 L18
  coincident P18 L19
  tangent L18 A1
  tangent L19 A1
  coincident P1 P24
  perpendicular L1 L20
  symmetric P3 L20 P37
  symmetric P4 L20 P39
  symmetric P5 L20 P35
  symmetric P6 L20 P38
  symmetric P7 L20 P40
  symmetric P8 L20 P36
  symmetric P9 L20 P31
  symmetric P10 L20 P28
  symmetric P11 L20 P30
  symmetric P12 L20 P33
  symmetric P13 L20 P27
  symmetric P14 L20 P32
  symmetric P15 L20 P29
  symmetric P16 L20 P26
  symmetric P18 L20 P34
  coincident L3 P41
  perpendicular L3 L35
  coincident L23 P42
  perpendicular L23 L36
  midpoint L37 P43
  perpendicular L37 L38
  perpendicular L38 L39
  perpendicular L37 L40
  perpendicular L40 L41
  perpendicular L41 L42
  coincident L37 P47
  coincident L6 P48
  perpendicular L6 L43
  coincident L6 P49
  coincident L37 P50
  perpendicular L37 L44
  coincident L45 P51
  coincident L46 P52
  concentric C2 C3
  coincident C3 P55
  horizontal L49
  coincident C3 P56
  coincident L27 P57
  tangent C3 L48
  symmetric P3 L20 P60
  symmetric P17 L20 P59
  symmetric P19 L20 P61
  symmetric P21 L20 P62
  coincident P34 P63
  horizontal L47
  coincident P54 P64
  perpendicular L29 L55
  coincident L10 P65
  perpendicular L10 L57
  coincident L19 P68
  parallel L56 L58
  parallel L16 L56
  collinear L9 L57
  symmetric L20 P65 P70
  symmetric L20 P66 P69
  vertical L60
  coincident L53 P72
  parallel L59 L61
  dimension "d12_1" distance P2 P3 = 32.5 (= "InnerBoxDepth / 2 - InnerChamferSize")
  dimension "d13_1" distance P3 P4 = 2.4 (= "WallThickness")
  dimension "d15_1" distance P5 P6 = 1.23
  dimension "d16_1" distance P6 P7 = 2
  dimension "d17_1" distance P7 P8 = 1.8
  dimension "d18_1" distance P8 P9 = 2
  dimension "d19" distance P9 P10 = 1.23
  dimension "d20_1" distance P10 P11 = 3
  dimension "d23_1" distance P12 P13 = 4.4
  dimension "d26_1" distance L15 L16 = 2.4 (= "WallThickness")
  dimension "d27_1" distance P4 P14 = 1 (= "InnerChamferSize")
  dimension "d28_1" distance P4 P14 = 1 (= "InnerChamferSize")
  dimension "d29_1" distance P3 L8 = 20.4 (= "InnerBoxLidHeight + WallThickness")
  dimension "d30_1" distance L16 L17 = 6.5
  dimension "d61_1" distance P10 P18 = 7
  dimension "d62_1" radius A1 = 5
  dimension "d63_1" diameter C1 = 3.4 (= "ScrewDiameter + HingeLatchHolesTolerance")
  dimension "d64_1" distance L18 P23 = 8 (= "LatchDistance / 2")
  dimension "d65_1" distance L19 P23 = 4.5
  dimension "d134" distance L3 L13 = 2.4 (= "WallThickness")
  dimension "d135" distance L5 L43 = 0.15
  dimension "d136" distance L7 L44 = 0.15
  dimension "d137_1" angle L45 L46 = 79.611
  dimension "d138_1" distance P46 P51 = 0.24
  dimension "d139_1" distance P45 P52 = 0.24
  dimension "d156" diameter C2 = 3.4 (= "ScrewDiameter + HingeLatchHolesTolerance")
  dimension "d157" distance P28 P53 = 3.6 (= "HingeOuterDiameter / 2 + 0.2 mm")
  dimension "d158" diameter C3 = 6.8 (= "HingeOuterDiameter")
  dimension "d159" angle L48 L49 = 45
  dimension "d116" distance L9 L12 = 1.86
  dimension "d117" distance L16 L56 = 1.86 (= "d116")
  dimension "d118" distance L18 P68 = 10 (= "LidLatchRibChamferOffset")
  dimension "d125" distance L55 P72 = 5 (= "HingeRibChamferOffset")
extrude "Extrude1" new body sketch "Sketch1" profile of L1 L2 L3 L4 A1 A2 A3 A4 along a picked direction blind 2.4 (= "WallThickness") named "d31_1" bodies "Box Waterproof"
sweep "Sweep1" sketch "Sketch2" TwistAngle 0 named "d37_1" TaperAngle 0 named "d38_1"
work_plane "WorkPlane2" AlongDistance -16.5 (= "RibOffset - InnerBoxDepth / 2") named "d46_1"
sketch "Sketch4" plane through (-16.5, 0, 0) normal (1, 0, 0) x axis (0, 0, -1)
  line L1 (-96.5, 0) -> (0, 0)
  line L2 (-96.5, 2.4) -> (-96.5, 0)
  line L3 (-97.5, 2.4) -> (-96.5, 2.4)
  line L4 (-97.5, 3.4) -> (-97.5, 2.4)
  line L5 (-96.5, 2.4) -> (-97.5, 3.4)
  line L6 (-97.5, 5) -> (-97.5, 2.4)
  line L7 (-97.5, 17.4) -> (-97.5, 2.4)
  line L8 (-101.76, 17.4) -> (-97.5, 17.4)
  line L9 (-101.76, 1.6355) -> (-101.76, 17.4)
  line L10 (-96.5, 0) -> (-100.1245, 0)
  line L11 (-101.76, 1.6355) -> (-100.1245, 0)
  line L12 (0, 70) -> (0, 0)
  line L13 (101.76, 1.6355) -> (100.1245, 0)
  line L14 (96.5, 0) -> (100.1245, 0)
  line L15 (97.5, 5) -> (97.5, 2.4)
  line L16 (97.5, 17.4) -> (97.5, 2.4)
  line L17 (96.5, 2.4) -> (97.5, 3.4)
  line L18 (97.5, 3.4) -> (97.5, 2.4)
  line L19 (101.76, 17.4) -> (97.5, 17.4)
  line L20 (101.76, 1.6355) -> (101.76, 17.4)
  line L21 (96.5, 2.4) -> (96.5, 0)
  line L22 (97.5, 2.4) -> (96.5, 2.4)
  point P1 (0, 0)
  point P2 (0, 0)
  point P7 (-97.5, 5)
  point P12 (0, 0)
  point P3 (-96.5, 0)
  point P16 (96.5, 0)
  point P4 (-96.5, 2.4)
  point P18 (96.5, 2.4)
  point P5 (-97.5, 2.4)
  point P15 (97.5, 2.4)
  point P6 (-97.5, 3.4)
  point P17 (97.5, 3.4)
  point P22 (97.5, 5)
  point P8 (-97.5, 17.4)
  point P14 (97.5, 17.4)
  point P9 (-101.76, 17.4)
  point P19 (101.76, 17.4)
  point P10 (-101.76, 1.6355)
  point P21 (101.76, 1.6355)
  point P11 (-100.1245, 0)
  point P20 (100.1245, 0)
  coincident P1 P2
  horizontal L1
  perpendicular L1 L2
  perpendicular L2 L3
  perpendicular L3 L4
  coincident L4 P7
  perpendicular L3 L7
  perpendicular L7 L8
  perpendicular L8 L9
  perpendicular L2 L10
  coincident P1 P12
  perpendicular L1 L12
  symmetric P3 L12 P16
  symmetric P4 L12 P18
  symmetric P5 L12 P15
  symmetric P6 L12 P17
  symmetric P7 L12 P22
  symmetric P8 L12 P14
  symmetric P9 L12 P19
  symmetric P10 L12 P21
  symmetric P11 L12 P20
  dimension "d47_1" distance P2 P3 = 96.5 (= "InnerBoxWidth / 2 - InnerChamferSize")
  dimension "d48_1" distance P3 P4 = 2.4 (= "WallThickness")
  dimension "d49_1" distance P4 P5 = 1 (= "InnerChamferSize")
  dimension "d50_1" distance P5 P6 = 1 (= "InnerChamferSize")
  dimension "d52_1" distance P8 P9 = 4.26
  dimension "d53_1" distance L5 L11 = 4.26 (= "d52_1")
  dimension "d56_1" distance L8 L10 = 17.4 (= "InnerBoxLidHeight - 3 mm + WallThickness")
extrude "Extrude2" add sketch "Sketch4" profile of L2 L3 L4 L5 L6 L7 L8 L9 L10 L11 L13 L14 L15 L16 L17 L18 L19 L20 L21 L22 along a picked direction blind 5 (= "RibWidth") named "d54_1" bodies "Box Waterproof"
work_plane "WorkPlane3" AlongDistance 16.5 (= "InnerBoxDepth / 2 - RibOffset") named "d57_1"
sketch "Sketch5" plane through (16.5, 0, 0) normal (1, 0, 0) x axis (0, 0, -1)
  line L1 (-97.5, 17.4) -> (-97.5, 2.4)
  line L2 (-96.5, 2.4) -> (-97.5, 3.4)
  line L3 (-97.5, 2.4) -> (-96.5, 2.4)
  line L4 (-96.5, 2.4) -> (-96.5, 0)
  line L5 (-96.5, 0) -> (-100.1245, 0)
  line L6 (-101.76, 1.6355) -> (-100.1245, 0)
  line L7 (-101.76, 1.6355) -> (-101.76, 17.4)
  line L8 (-101.76, 17.4) -> (-97.5, 17.4)
  line L9 (101.76, 17.4) -> (97.5, 17.4)
  line L10 (101.76, 1.6355) -> (101.76, 17.4)
  line L11 (97.5, 17.4) -> (97.5, 2.4)
  line L12 (96.5, 2.4) -> (97.5, 3.4)
  line L13 (97.5, 2.4) -> (96.5, 2.4)
  line L14 (101.76, 1.6355) -> (100.1245, 0)
  line L15 (96.5, 2.4) -> (96.5, 0)
  line L16 (96.5, 0) -> (100.1245, 0)
extrude "Extrude3" add sketch "Sketch5" along a picked direction no distance stored
work_plane "WorkPlane4" AlongDistance -82.5 (= "HingeLatchOffset - InnerBoxWidth / 2") named "d60_1"
sketch "Sketch6" plane through (0, 0, -82.5) normal (0, 0, 1) x axis (1, 0, 0)
  line L1 (39.76, 20.4) -> (37.76, 20.4)
  line L2 (44.76, 2.0735) -> (44.76, 15.4)
  line L3 (44.76, 2.0735) -> (42.6865, 0)
  line L4 (32.5, 0) -> (42.6865, 0)
  line L5 (32.5, 2.4) -> (32.5, 0)
  line L6 (32.5, 2.4) -> (33.5, 3.4)
  line L7 (33.5, 20.4) -> (33.5, 3.4)
  line L8 (33.5, 17.4) -> (35.9, 17.4)
  line L9 (35.9, 17.4) -> (37.76, 17.4)
  line L10 (37.76, 17.4) -> (37.76, 20.4)
  line L11 (44.76, 10.4) -> (37.76, 3.4)
  line L12 (37.76, 3.4) -> (37.76, 1.6355)
  line L13 (37.76, 1.6355) -> (36.1245, 0)
  arc A1 centre (39.76, 15.4) radius 5 clockwise from (39.76, 20.4) to (44.76, 15.4)
  circle C1 centre (40.26, 12.4) radius 1.7
extrude "Extrude10" add sketch "Sketch6" profile of L1 L2 A1 L4 L5 L6 L7 L8 L9 L10 C1 L11 L12 L13 along a picked direction blind 3.2 (= "HingeLatchRibWidth") named "d81_1"
work_plane "WorkPlane5" AlongDistance 30 (= "ScrewLength") named "d68_1"
sketch "Sketch7" plane through (0, 0, -52.5) normal (0, 0, 1) x axis (1, 0, 0)
  line L1 (32.5, 2.4) -> (32.5, 0)
  line L2 (32.5, 2.4) -> (33.5, 3.4)
  line L3 (33.5, 20.4) -> (33.5, 3.4)
  line L4 (33.5, 17.4) -> (35.9, 17.4)
  line L5 (35.9, 17.4) -> (37.76, 17.4)
  line L6 (37.76, 17.4) -> (37.76, 20.4)
  line L7 (39.76, 20.4) -> (37.76, 20.4)
  line L8 (44.76, 2.0735) -> (44.76, 15.4)
  line L9 (44.76, 2.0735) -> (42.6865, 0)
  line L10 (32.5, 0) -> (42.6865, 0)
  line L11 (44.76, 10.4) -> (37.76, 3.4)
  line L12 (37.76, 3.4) -> (37.76, 1.6355)
  line L13 (37.76, 1.6355) -> (36.1245, 0)
  arc A1 centre (39.76, 15.4) radius 5 clockwise from (39.76, 20.4) to (44.76, 15.4)
  circle C1 centre (40.26, 12.4) radius 1.7
  circle C2 centre (40.26, 12.4) radius 1.425
  concentric C1 C2
  dimension "d41" diameter C2 = 2.85 (= "ScrewThreadDiameter")
extrude "Extrude11" add sketch "Sketch7" profile of L1 L2 L3 L4 L5 L6 L7 A1 L8 L10 C2 L11 L12 L13 along a picked direction no distance stored
work_plane "WorkPlane6" AlongDistance 82.5 (= "-( HingeLatchOffset - InnerBoxWidth / 2 )") named "d71_1"
sketch "Sketch8" plane through (0, 0, 82.5) normal (0, 0, 1) x axis (1, 0, 0)
  line L1 (32.5, 2.4) -> (32.5, 0)
  line L2 (32.5, 2.4) -> (33.5, 3.4)
  line L3 (33.5, 20.4) -> (33.5, 3.4)
  line L4 (33.5, 17.4) -> (35.9, 17.4)
  line L5 (35.9, 17.4) -> (37.76, 17.4)
  line L6 (37.76, 17.4) -> (37.76, 20.4)
  line L7 (39.76, 20.4) -> (37.76, 20.4)
  line L8 (44.76, 2.0735) -> (44.76, 15.4)
  line L9 (44.76, 2.0735) -> (42.6865, 0)
  line L10 (32.5, 0) -> (42.6865, 0)
  line L11 (44.76, 10.4) -> (37.76, 3.4)
  line L12 (37.76, 3.4) -> (37.76, 1.6355)
  line L13 (37.76, 1.6355) -> (36.1245, 0)
  arc A1 centre (39.76, 15.4) radius 5 clockwise from (39.76, 20.4) to (44.76, 15.4)
  circle C1 centre (40.26, 12.4) radius 1.7
extrude "Extrude12" add sketch "Sketch8" profile of L1 L2 L3 L4 L5 L6 L7 A1 L8 C1 L10 L11 L12 L13 along a picked direction no distance stored
work_plane "WorkPlane7"
sketch "Sketch9" plane through (0, 0, 52.5) normal (0, 0, 1) x axis (1, 0, 0)
  line L1 (44.76, 2.0735) -> (42.6865, 0)
  line L2 (32.5, 0) -> (42.6865, 0)
  line L3 (44.76, 2.0735) -> (44.76, 15.4)
  line L4 (39.76, 20.4) -> (37.76, 20.4)
  line L5 (37.76, 17.4) -> (37.76, 20.4)
  line L6 (35.9, 17.4) -> (37.76, 17.4)
  line L7 (33.5, 17.4) -> (35.9, 17.4)
  line L8 (33.5, 20.4) -> (33.5, 3.4)
  line L9 (32.5, 2.4) -> (33.5, 3.4)
  line L10 (32.5, 2.4) -> (32.5, 0)
  line L11 (44.76, 10.4) -> (37.76, 3.4)
  line L12 (37.76, 3.4) -> (37.76, 1.6355)
  line L13 (37.76, 1.6355) -> (36.1245, 0)
  arc A1 centre (39.76, 15.4) radius 5 clockwise from (39.76, 20.4) to (44.76, 15.4)
  circle C1 centre (40.26, 12.4) radius 1.7
  circle C2 centre (40.26, 12.4) radius 1.425
  concentric C1 C2
  dimension "d42" diameter C2 = 2.85 (= "ScrewThreadDiameter")
extrude "Extrude13" add sketch "Sketch9" profile of L2 L3 A1 L4 L5 L6 L7 L8 L9 L10 C2 L11 L12 L13 along a picked direction blind 3.2 (= "HingeLatchRibWidth") named "d87_1"
work_plane "WorkPlane8" AlongDistance -67.5 (= "HingeLatchOffset - InnerBoxWidth / 2 + ScrewLength / 2")
sketch "Sketch12" plane through (0, 0, -67.5) normal (0, 0, 1) x axis (1, 0, 0)
  line L1 (-35.9, 10.1317) -> (-43.7642, 17.9958)
  line L2 (-37.96, 20.4) -> (-37.76, 20.4)
  line L3 (-37.76, 17.4) -> (-37.76, 20.4)
  line L4 (-37.76, 17.4) -> (-35.9, 13)
  line L5 (-35.9, 2.4059) -> (-35.9, 13)
  line L6 (-44.76, 2.0735) -> (-44.76, 15.4)
  line L7 (-44.76, 20.4) -> (-44.76, 15.4)
  line L8 (-44.76, 2.0735) -> (-42.6865, 0)
  line L9 (-32.5, 0) -> (-42.6865, 0)
  line L10 (-35.9, 2.4059) -> (-33.4941, 0)
  line L11 (-37.76, 1.6355) -> (-36.1245, 0)
  line L12 (-44.76, 15.4) -> (-37.76, 8.4)
  line L13 (-37.76, 8.4) -> (-37.76, 1.6355)
  circle C1 centre (-41.36, 20.4) radius 3.4
  circle C2 centre (-41.36, 20.4) radius 1.7
extrude "Extrude19" add sketch "Sketch12" profile of L1 C1 C2 L2 L3 L4 L5 along a picked direction no distance stored
extrude "Extrude21" add sketch "Sketch12" profile of L1 C1 L5 L6 L7 L9 L10 L12 L13 L11 along a picked direction distance 1.6 (= "HingeLatchRibWidth / 2")
work_plane "WorkPlane9" AlongDistance 67.5 (= "InnerBoxWidth / 2 - HingeLatchOffset - ScrewLength / 2")
sketch "Sketch13" plane through (0, 0, 67.5) normal (0, 0, 1) x axis (1, 0, 0)
  line L1 (-35.9, 10.1317) -> (-43.7642, 17.9958)
  line L2 (-37.76, 17.4) -> (-35.9, 13)
  line L3 (-35.9, 2.4059) -> (-35.9, 13)
  line L4 (-37.76, 17.4) -> (-37.76, 20.4)
  line L5 (-37.96, 20.4) -> (-37.76, 20.4)
  line L6 (-44.76, 2.0735) -> (-44.76, 15.4)
  line L7 (-44.76, 20.4) -> (-44.76, 15.4)
  line L8 (-44.76, 2.0735) -> (-42.6865, 0)
  line L9 (-32.5, 0) -> (-42.6865, 0)
  line L10 (-35.9, 2.4059) -> (-33.4941, 0)
  line L11 (-37.76, 1.6355) -> (-36.1245, 0)
  line L12 (-44.76, 15.4) -> (-37.76, 8.4)
  line L13 (-37.76, 8.4) -> (-37.76, 1.6355)
  circle C1 centre (-41.36, 20.4) radius 3.4
  circle C2 centre (-41.36, 20.4) radius 1.7
extrude "Extrude20" add sketch "Sketch13" profile of L1 L2 L3 L4 C1 C2 L5 along a picked direction no distance stored
extrude "Extrude22" add sketch "Sketch13" profile of L1 L3 C1 L6 L7 L9 L10 L12 L13 L11 along a picked direction distance 1.6 (= "HingeLatchRibWidth / 2")
fillet "Fillet2" radius 1
fillet "Fillet3" radius 3
chamfer "Chamfer3" distance 0.6 distance 5
component_from_bodies "Body->Comp1"
joint "Assemble1" alignAngle 180 alignOffsetX 0 alignOffsetY 0 alignOffsetZ 0.125 (= "HingeWidthTolerance / 2") AngleMinimum -180 AngleMaximum 0
sketch "Sketch1" plane through (0, 0, 73.4) normal (0, 0, 1) x axis (-1, 0, 0)
extrude "Extrude1" new body of existing geometry blind 1.4 (= "SealHeight") bodies "Box - Seal"
ground "Ground1"
joint "Assemble2" alignAngle 180 alignOffsetX 0 alignOffsetY 0 alignOffsetZ 0.2 (= "LatchWidthTolerance / 2") AngleMinimum 0 AngleMaximum 185
chamfer "Chamfer1" distance 0.4
mirror "Mirror2" mirrorStitchTolerance 0.1 bodies "Box - Latch (1)"
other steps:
base_feature "Base Feature1" bodies "Box - Lid"
base_feature "Base Feature1" bodies "Box Waterproof", "Box - Bottom"
base_feature "Base Feature1" bodies "Latch", "Box - Latch"
create_component "CreateComponent1"
remove_body "RemoveBody1"
create_component "CreateComponent3"
remove_body "RemoveBody3"
create_component "CreateComponent1"
create_component "CreateComponent1"
remove_body "RemoveBody1"
create_component "CreateComponent2"
joint_origin "JointOrigin2"
joint_origin "JointOrigin2"
create_component "CreateComponent3"
joint_origin "JointOrigin2"
joint_origin "JointOrigin4"
named bodies: "Box Waterproof", "Latch", "Box - Latch", "Box - Bottom", "Box - Lid", "Box - Seal", "Box - Latch (1)"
